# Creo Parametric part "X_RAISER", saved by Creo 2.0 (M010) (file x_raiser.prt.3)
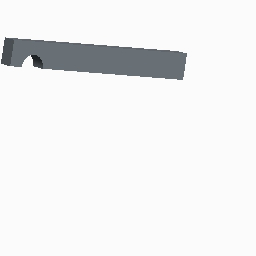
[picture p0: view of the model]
Units: Inch lbm Second (Pro/E Default); INCH, POUND, SECS

Created from: INLBS_PART_SOLID.PRT

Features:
  1. datum plane "RIGHT"
  2. datum plane "TOP"
  3. datum plane "FRONT"
  4. coordinate system
  5. sketch "Sketch 1"
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
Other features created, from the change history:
  extrusion "Extrude 1"
  sketch "Sketch 2"
  extruded cut "Extrude 2"

Surfaces: 9 plane, 1 cylinder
